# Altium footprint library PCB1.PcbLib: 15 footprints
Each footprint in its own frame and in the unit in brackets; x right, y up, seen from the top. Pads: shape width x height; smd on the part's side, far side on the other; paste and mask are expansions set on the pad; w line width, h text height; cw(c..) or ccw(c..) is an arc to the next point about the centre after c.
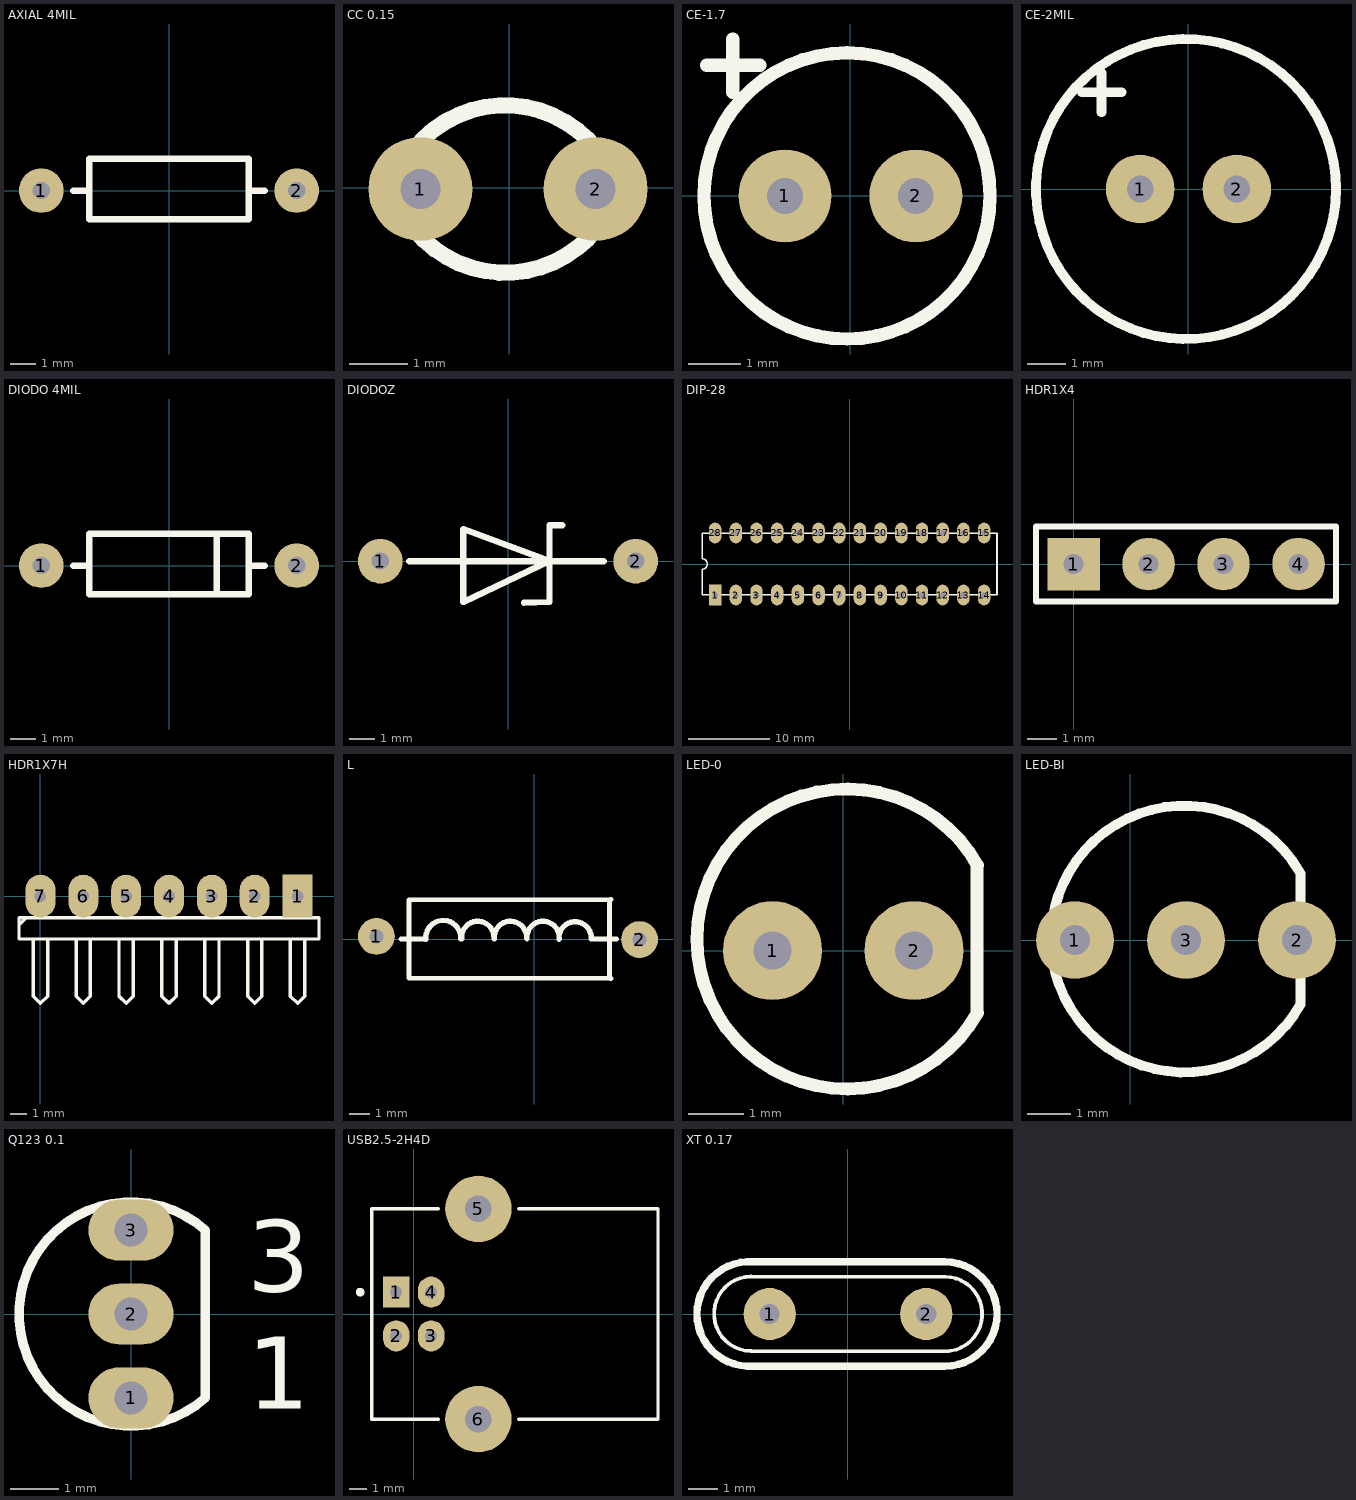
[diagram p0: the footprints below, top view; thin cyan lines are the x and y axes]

## AXIAL 4MIL [mil]
pads (2):
  round 70 hole 27: 1(-200,0) 2(200,0)
Top Overlay:
  lines w10: -150,0 -130,0 ; 130,0 150,0 ; -125,-45 -125,50 125,50 125,-45 -125,-45

## CC 0.15 [mil]
pads (2):
  round 70 hole 27: 1(-59.78,-1) 2(58.33,-1)
Top Overlay:
  lines w11: -73.89,10.1 cw(c-2.6,-23.32) 69.01,9.42 ; -69,-21 ccw(c-2.6,21.32) 69.01,-11.42

## CE-1.7 [mil]
pads (2):
  round 70 hole 27: 1(-49,0) 2(49.43,0)
Top Overlay:
  circle w10: c-2.33,0 r107.67
  lines w10: -108.06,98.43 -68.06,98.43 ; -88.37,78.12 -88.37,118.12

## CE-2MIL [mil]
pads (2):
  round 70 hole 27: 1(-49,0) 2(49.43,0)
Top Overlay:
  circle w10: c-2.33,0 r152.67
  lines w10: -108.06,98.43 -68.06,98.43 ; -88.37,78.12 -88.37,118.12

## DIODO 4MIL [mil]
pads (2):
  round 70 hole 27: 1(-200,0) 2(200,0)
Top Overlay:
  lines w10: -150,0 -130,0 ; 75,-45 75,50 ; 130,0 150,0 ; -125,-45 125,-45 125,50 -125,50 -125,-45

## DIODOZ [mil]
pads (2):
  round 70 hole 27: 1(-200,0) 2(200,0)
Top Overlay:
  lines w10: -155,0 65,0 ; 25,-65 65,-64 65,56 85,56 ; 150,0 65,0 ; 65,0 -70,-64 -70,50 65,0

## DIP-28 [mil]
pads (28):
  rect 60x100 hole 27: 1(-650,-150)
  oval 60x100 hole 27: 2(-550,-150) 3(-450,-150) 4(-350,-150) 5(-250,-150) 6(-150,-150) 7(-50,-150) 8(50,-150) 9(150,-150) 10(250,-150) 11(350,-150) 12(450,-150) 13(550,-150) 14(650,-150) 15(650,150) 16(550,150) 17(450,150) 18(350,150) 19(250,150) 20(150,150) 21(50,150) 22(-50,150) 23(-150,150) 24(-250,150) 25(-350,150) 26(-450,150) 27(-550,150) 28(-650,150)
Top Overlay:
  lines w7.87: -712.6,-149.33 -712.6,-25 ccw(c-712.6,0) -712.6,25 -712.6,149.33 712.6,149.33 712.6,-149.33 -712.6,-149.33

## HDR1X4 [mil]
pads (4):
  rect 70x70 hole 27: 1(0,0)
  round 70 hole 27: 2(100,0) 3(200,0) 4(300,0)
Top Overlay:
  lines w7.87: -50,-50 350,-50 350,50 -50,50 -50,-50

## HDR1X7H [mil]
pads (7):
  rect 70x100 hole 27: 1(600,0)
  oval 70x100 hole 27: 2(500,0) 3(400,0) 4(300,0) 5(200,0) 6(100,0) 7(0,0)
Top Overlay:
  lines w7.87: -50,-66.67 -33.33,-50 ; -16.67,-100 -16.67,-233.33 0,-250 16.67,-233.33 16.67,-100 ; 83.33,-100 83.33,-233.33 100,-250 116.67,-233.33 116.67,-100 ; 183.33,-100 183.33,-233.33 200,-250 216.67,-233.33 216.67,-100 ; 283.33,-100 283.33,-233.33 300,-250 316.67,-233.33 316.67,-100 ; 383.33,-100 383.33,-233.33 400,-250 416.67,-233.33 416.67,-100 ; 483.33,-100 483.33,-233.33 500,-250 516.67,-233.33 516.67,-100 ; 583.33,-100 583.33,-233.33 600,-250 616.67,-233.33 616.67,-100 ; -50,-100 650,-100 650,-50 -50,-50 -50,-100

## L [mil]
pads (2):
  round 70 hole 27: 1(-300,5) 2(200,-1)
Top Overlay:
  lines w10: -253,0 -210,0 ; -206.14,-1.07 cw(c-173.12,2.26) -140,0 ; -138,0 cw(c-107.44,3.08) -76.79,0.99 ; -76,0 cw(c-45.44,3.08) -14.79,0.99 ; -14,0 cw(c16.56,3.08) 47.21,0.99 ; 47,-1 cw(c77.56,2.08) 108.21,-0.01 ; 110,0 156,0 ; 143,-72 143,71 ; 145,-75 -238,-74 -238,74 145,75

## LED-0 [mil]
pads (2):
  round 70 hole 27: 1(-50,0) 2(50,0)
Top Overlay:
  lines w9: 94.49,-43.9 94.49,60.04 ; 94.88,-43.96 cw(c2.59,8.19) 94.91,60.28

## LED-BI [mil]
pads (3):
  round 70 hole 27: 1(-50,0) 2(150,0) 3(50,0)
Top Overlay:
  lines w9: 151.73,62.28 ccw(c48.57,0.98) 153,-58.13 ; 153,-56 153,60

## Q123 0.1 [mil]
pads (3):
  oval 70x50 hole 27: 1(0,-68.9) 2(0,0) 3(0,68.9)
Top Overlay:
  lines w7.87: 61.02,-68.9 cw(c0,0) 61.02,68.9 61.02,-68.9
  text "3" at 95.31,18.39 h59.05
  text "1" at 95.31,-77.91 h59.05

## USB2.5-2H4D [mil]
pads (6):
  rect 60x70 hole 27: 1(-39.37,49.21)
  oval 60x70 hole 27: 2(-39.37,-49.21) 3(39.37,-49.21) 4(39.37,49.21)
  round 149.61 hole 60: 5(146.06,237.01) 6(146.06,-237.01)
Top Overlay:
  circle w9.84: c-120.47,49.21 r4.92
  lines w7.87: 55.51,-237.01 -94.88,-237.01 -94.88,237.01 55.51,237.01 ; 236.61,-237.01 550.79,-237.01 550.79,237.01 236.61,237.01

## XT 0.17 [mil]
pads (2):
  round 70 hole 27: 1(-105,0) 2(105,0)
Top Overlay:
  lines w5: -130,-50 135,-50 ; -130,-49.7 cw(c-129.59,0.29) -130,50.29 ; -130,50 130,50 cw(c129.83,0) 130,-50
  lines w10: -135,-70 130,-70 ccw(c129.76,0) 130,70 -135,70 ccw(c-132.41,0.05) -135,-69.9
